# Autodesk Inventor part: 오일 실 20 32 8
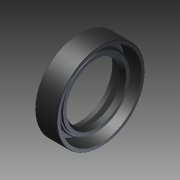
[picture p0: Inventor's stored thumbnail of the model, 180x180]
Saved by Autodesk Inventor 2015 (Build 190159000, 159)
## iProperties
Created: 2024-12
Part Number: 오일 실 20 32 8
Material: 일반
Document SubType Name: Modeling
Designer: 10401
Density: 1 g/cm^3
Appearance: 기본값
Author: 10401
Author: jhkim
Description: 오일-실
Creation Date: 2024-11-28
Sending System: Autodesk Inventor 2025
Preprocessor: ST-DEVELOPER v20
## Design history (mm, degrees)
node "오일 실 20 32 81"
body "Solid1"
node "기준1"
